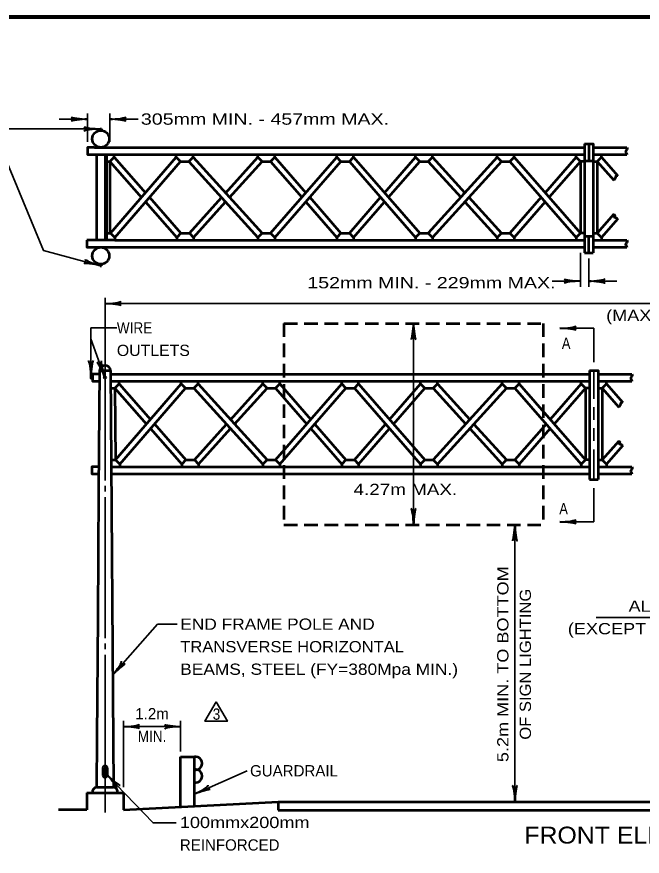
# Model space of a CAD drawing. Extents: x -35 to 821, y -13 to 531.
# Drawn here: x 165.2 to 298.4, y 346.2 to 525.1 of the extents above; entities that cross this region are included whole.
import ezdxf
from ezdxf.enums import TextEntityAlignment as Align

# ---------------------------------------------------------------- set-up
doc = ezdxf.new("R2010")
doc.units = 0
doc.header["$LTSCALE"] = 0.96
doc.linetypes.add('MEDIUM_DASHED', pattern=[4.5, 3, -1.5])
doc.layers.add('1', color=7, linetype='Continuous', lineweight=53)

msp = doc.modelspace()

# ---------------------------------------------------------------- linework, layer by layer
at = {"layer": '1', "lineweight": 35}
for p, q in [((180.2699, 498.4681), (180.2699, 504.4681)), ((185.0851, 498.4681), (185.0851, 504.4681)), ((174.2699, 503.2681), (180.2699, 503.2681)), ((185.0851, 503.2681), (191.0851, 503.2681)), ((285.2699, 474.7681), (285.2699, 467.5681)), ((287.0699, 473.5681), (287.0699, 467.5681)), ((285.2699, 468.7681), (279.2699, 468.7681)), ((287.0699, 468.7681), (293.0699, 468.7681)), ((184.0361, 426.3181), (184.0361, 465.1682)), ((184.0361, 463.9682), (413.7457, 463.9682)), ((249.7361, 459.7681), (249.7361, 416.8681)), ((181.0361, 448.3681), (181.0384, 458.8371)), ((181.0384, 458.8371), (186.5374, 458.8309)), ((288.1361, 458.7181), (280.9361, 458.7181)), ((288.1361, 451.5181), (288.1361, 458.7181)), ((181.0379, 456.4728), (183.9531, 448.343)), ((288.1361, 449.7181), (288.1361, 443.7181)), ((288.1361, 441.9181), (288.1361, 439.2181)), ((288.1361, 437.4181), (288.1361, 434.7181)), ((288.1361, 432.9181), (288.1361, 426.4681)), ((184.0361, 423.9181), (184.0361, 425.1181)), ((288.1361, 424.6681), (288.1361, 417.4681)), ((184.0361, 392.7181), (184.0361, 422.7181)), ((271.3361, 416.8681), (271.3361, 357.8452)), ((288.1361, 417.4681), (280.9361, 417.4681)), ((288.6341, 397.0681), (396.0341, 397.0681)), ((184.0361, 390.3181), (184.0361, 391.5181)), ((184.0361, 355.5181), (184.0361, 389.1181)), ((187.9361, 360.9181), (187.9361, 375.0433)), ((187.9361, 373.8433), (200.1229, 373.8433)), ((200.1229, 368.5706), (200.1229, 375.0433)), ((203.0564, 359.4792), (214.3126, 364.3926))]:
    msp.add_line(p, q, dxfattribs=at)
at = {"layer": '1'}
for p, q in [((182.9861, 501.1801), (183.2861, 501.1801)), ((182.9861, 500.8739), (182.9861, 501.1801)), ((183.2861, 501.1801), (183.2861, 500.8739)), ((181.7648, 497.2681), (286.1699, 497.2681)), ((286.1699, 498.0181), (286.1699, 474.7681)), ((287.0699, 498.0181), (287.0699, 494.4181)), ((287.9699, 497.2681), (295.1699, 497.2681)), ((182.2361, 495.7681), (182.2361, 477.4681)), ((184.0361, 495.7681), (184.0361, 477.4681)), ((184.3361, 495.7681), (184.3361, 477.4681)), ((185.9851, 495.1681), (185.9851, 495.7681)), ((185.9851, 495.7681), (233.3775, 495.7681)), ((199.1851, 495.1681), (199.1851, 495.7681)), ((202.7851, 495.1681), (202.7851, 495.7681)), ((216.5775, 495.1681), (216.5775, 495.7681)), ((220.1775, 495.1681), (220.1775, 495.7681)), ((233.3775, 495.1681), (233.3775, 495.7681)), ((236.9775, 495.1681), (236.9775, 495.7681)), ((250.1775, 495.1681), (250.1775, 495.7681)), ((253.7775, 495.1681), (253.7775, 495.7681)), ((267.5699, 495.1681), (267.5699, 495.7681)), ((271.1699, 495.1681), (271.1699, 495.7681)), ((284.3699, 495.1681), (284.3699, 495.7681)), ((287.9699, 495.7681), (295.1699, 495.7681)), ((289.7699, 495.1681), (289.7699, 495.7681)), ((184.3361, 494.2681), (185.0851, 494.2681)), ((185.0851, 494.2681), (185.9851, 495.1681)), ((185.0851, 494.2681), (191.8053, 486.6142)), ((185.0851, 494.2681), (185.0851, 478.9681)), ((185.2088, 478.9681), (199.1851, 495.1681)), ((185.9851, 495.1681), (192.643, 487.5851)), ((186.1088, 478.0681), (200.0851, 494.2681)), ((200.0851, 494.2681), (199.1851, 495.1681)), ((201.8851, 494.2681), (202.7851, 495.1681)), ((201.8851, 494.2681), (216.5775, 478.0681)), ((202.7851, 495.1681), (217.4775, 478.9681)), ((209.7105, 487.5321), (216.5775, 495.1681)), ((210.5687, 486.5858), (217.4775, 494.2681)), ((217.4775, 494.2681), (216.5775, 495.1681)), ((219.2775, 478.9681), (233.3775, 495.1681)), ((219.2775, 494.2681), (220.1775, 495.1681)), ((219.2775, 494.2681), (225.9358, 486.6181)), ((220.1775, 495.1681), (226.7775, 487.5851)), ((220.1775, 478.0681), (234.2775, 494.2681)), ((234.2775, 494.2681), (233.3775, 495.1681)), ((236.0775, 494.2681), (236.9775, 495.1681)), ((236.0775, 494.2681), (250.1775, 478.0681)), ((236.9775, 495.1681), (251.0775, 478.9681)), ((243.5775, 487.5851), (250.1775, 495.1681)), ((244.4192, 486.6181), (251.0775, 494.2681)), ((251.0775, 494.2681), (250.1775, 495.1681)), ((252.8775, 494.2681), (253.7775, 495.1681)), ((267.5699, 495.1681), (252.8775, 478.9681)), ((252.8775, 494.2681), (259.8156, 486.6181)), ((253.7775, 495.1681), (260.6737, 487.5643)), ((268.4699, 494.2681), (253.7775, 478.0681)), ((268.4699, 494.2681), (267.5699, 495.1681)), ((270.2699, 494.2681), (271.1699, 495.1681)), ((270.2699, 494.2681), (284.3699, 478.0681)), ((271.1699, 495.1681), (285.2699, 478.9681)), ((284.3699, 495.1681), (277.7699, 487.5851)), ((285.2699, 494.2681), (278.6115, 486.6181)), ((285.2699, 494.2681), (284.3699, 495.1681)), ((286.1699, 494.2681), (285.2699, 494.2681)), ((285.2699, 494.2681), (285.2699, 478.9681)), ((286.1699, 494.4181), (287.9699, 494.4181)), ((287.9699, 494.2681), (288.8699, 494.2681)), ((288.8699, 494.2681), (289.7699, 495.1681)), ((288.8699, 494.2681), (288.8699, 478.9681)), ((288.8699, 494.2681), (292.3771, 490.2387)), ((289.7699, 495.1681), (293.2187, 491.2057)), ((193.4886, 486.622), (200.2088, 478.9681)), ((202.0088, 478.9681), (208.856, 486.5819)), ((227.6192, 486.6181), (234.2775, 478.9681)), ((236.0775, 478.9681), (242.7359, 486.6181)), ((261.5318, 486.6181), (268.4699, 478.9681)), ((276.9283, 486.6181), (270.2699, 478.9681)), ((192.6509, 485.6511), (199.3088, 478.0681)), ((202.9088, 478.0681), (209.7143, 485.6356)), ((226.7775, 485.6511), (233.3775, 478.0681)), ((236.9775, 478.0681), (243.5775, 485.6511)), ((260.6737, 485.6719), (267.5699, 478.0681)), ((277.7699, 485.6511), (271.1699, 478.0681)), ((292.3769, 482.9973), (288.8699, 478.9681)), ((293.2185, 482.0303), (289.7699, 478.0681)), ((184.3361, 478.9681), (185.2088, 478.9681)), ((185.2088, 478.9681), (186.1088, 478.0681)), ((186.1088, 478.0681), (186.1088, 477.4681)), ((200.2088, 478.9681), (199.3088, 478.0681)), ((199.3088, 478.0681), (199.3088, 477.4681)), ((200.2088, 478.9681), (202.0088, 478.9681)), ((202.0088, 478.9681), (202.9088, 478.0681)), ((202.9088, 478.0681), (202.9088, 477.4681)), ((217.4775, 478.9681), (216.5775, 478.0681)), ((216.5775, 478.0681), (216.5775, 477.4681)), ((217.4775, 478.9681), (219.2775, 478.9681)), ((219.2775, 478.9681), (220.1775, 478.0681)), ((220.1775, 478.0681), (220.1775, 477.4681)), ((234.2775, 478.9681), (233.3775, 478.0681)), ((233.3775, 478.0681), (233.3775, 477.4681)), ((234.2775, 478.9681), (236.0775, 478.9681)), ((236.0775, 478.9681), (236.9775, 478.0681)), ((236.9775, 478.0681), (236.9775, 477.4681)), ((251.0775, 478.9681), (250.1775, 478.0681)), ((250.1775, 478.0681), (250.1775, 477.4681)), ((251.0775, 478.9681), (252.8775, 478.9681)), ((252.8775, 478.9681), (253.7775, 478.0681)), ((253.7775, 478.0681), (253.7775, 477.4681)), ((268.4699, 478.9681), (267.5699, 478.0681)), ((267.5699, 478.0681), (267.5699, 477.4681)), ((268.4699, 478.9681), (270.2699, 478.9681)), ((270.2699, 478.9681), (271.1699, 478.0681)), ((271.1699, 478.0681), (271.1699, 477.4681)), ((285.2699, 478.9681), (284.3699, 478.0681)), ((284.3699, 478.0681), (284.3699, 477.4681)), ((286.1699, 478.9681), (285.2699, 478.9681)), ((286.1699, 478.3681), (287.9699, 478.3681)), ((287.0699, 474.7681), (287.0699, 478.3681)), ((287.9699, 478.9681), (288.8699, 478.9681)), ((288.8699, 478.9681), (289.7699, 478.0681)), ((289.7699, 478.0681), (289.7699, 477.4681)), ((182.2361, 477.4681), (180.1361, 477.4681)), ((181.6209, 475.9681), (286.1699, 475.9681)), ((186.1088, 477.4681), (233.3775, 477.4681)), ((287.9699, 477.4681), (295.1699, 477.4681)), ((287.9699, 475.9681), (295.1699, 475.9681)), ((286.1699, 474.7681), (287.9699, 474.7681)), ((182.9861, 472.3561), (182.9861, 472.0561)), ((183.2861, 472.0561), (183.2861, 472.3561)), ((182.9861, 472.0561), (183.2861, 472.0561)), ((182.8361, 449.7181), (185.2361, 449.7181)), ((185.2361, 449.7181), (185.8361, 360.9181)), ((185.2361, 448.9681), (287.2361, 448.9681)), ((287.2361, 449.7181), (287.2361, 426.4681)), ((289.0361, 448.9681), (296.2361, 448.9681)), ((187.0513, 446.8681), (187.0513, 447.4681)), ((200.2513, 446.8681), (200.2513, 447.4681)), ((203.8513, 446.8681), (203.8513, 447.4681)), ((217.6437, 446.8681), (217.6437, 447.4681)), ((221.2437, 446.8681), (221.2437, 447.4681)), ((234.4437, 446.8681), (234.4437, 447.4681)), ((238.0437, 446.8681), (238.0437, 447.4681)), ((251.2437, 446.8681), (251.2437, 447.4681)), ((254.8437, 446.8681), (254.8437, 447.4681)), ((268.6361, 446.8681), (268.6361, 447.4681)), ((272.2361, 446.8681), (272.2361, 447.4681)), ((285.4361, 446.8681), (285.4361, 447.4681)), ((289.0361, 447.4681), (296.2361, 447.4681)), ((290.8361, 446.8681), (290.8361, 447.4681)), ((185.2513, 445.9681), (186.1513, 445.9681)), ((186.1513, 445.9681), (187.0513, 446.8681)), ((186.1513, 445.9681), (186.275, 430.6681)), ((186.1513, 445.9681), (192.8715, 438.3142)), ((186.275, 430.6681), (200.2513, 446.8681)), ((187.0513, 446.8681), (193.7092, 439.2851)), ((187.175, 429.7681), (201.1513, 445.9681)), ((201.1513, 445.9681), (200.2513, 446.8681)), ((202.9513, 445.9681), (203.8513, 446.8681)), ((202.9513, 445.9681), (217.6437, 429.7681)), ((203.8513, 446.8681), (218.5437, 430.6681)), ((210.7767, 439.2321), (217.6437, 446.8681)), ((211.6349, 438.2858), (218.5437, 445.9681)), ((218.5437, 445.9681), (217.6437, 446.8681)), ((220.3437, 445.9681), (221.2437, 446.8681)), ((220.3437, 430.6681), (234.4437, 446.8681)), ((220.3437, 445.9681), (227.002, 438.3181)), ((221.2437, 446.8681), (227.8437, 439.2851)), ((221.2437, 429.7681), (235.3437, 445.9681)), ((235.3437, 445.9681), (234.4437, 446.8681)), ((237.1437, 445.9681), (238.0437, 446.8681)), ((237.1437, 445.9681), (251.2437, 429.7681)), ((238.0437, 446.8681), (252.1437, 430.6681)), ((244.6437, 439.2851), (251.2437, 446.8681)), ((245.4854, 438.3181), (252.1437, 445.9681)), ((252.1437, 445.9681), (251.2437, 446.8681)), ((253.9437, 445.9681), (254.8437, 446.8681)), ((268.6361, 446.8681), (253.9437, 430.6681)), ((253.9437, 445.9681), (260.8818, 438.3181)), ((254.8437, 446.8681), (261.7399, 439.2643)), ((269.5361, 445.9681), (254.8437, 429.7681)), ((269.5361, 445.9681), (268.6361, 446.8681)), ((271.3361, 445.9681), (272.2361, 446.8681)), ((271.3361, 445.9681), (285.4361, 429.7681)), ((272.2361, 446.8681), (286.3361, 430.6681)), ((285.4361, 446.8681), (278.8361, 439.2851)), ((286.3361, 445.9681), (279.6777, 438.3181)), ((286.3361, 445.9681), (285.4361, 446.8681)), ((287.2361, 445.9681), (286.3361, 445.9681)), ((286.3361, 445.9681), (286.3361, 430.6681)), ((289.0361, 445.9681), (289.9361, 445.9681)), ((289.9361, 445.9681), (290.8361, 446.8681)), ((289.9361, 445.9681), (289.9361, 430.6681)), ((289.9361, 445.9681), (293.4433, 441.9387)), ((290.8361, 446.8681), (294.2849, 442.9057)), ((194.5548, 438.322), (201.275, 430.6681)), ((203.075, 430.6681), (209.9222, 438.2819)), ((228.6854, 438.3181), (235.3437, 430.6681)), ((237.1437, 430.6681), (243.8021, 438.3181)), ((262.598, 438.3181), (269.5361, 430.6681)), ((277.9945, 438.3181), (271.3361, 430.6681)), ((193.7171, 437.3511), (200.375, 429.7681)), ((203.975, 429.7681), (210.7805, 437.3356)), ((227.8437, 437.3511), (234.4437, 429.7681)), ((238.0437, 429.7681), (244.6437, 437.3511)), ((261.7399, 437.3719), (268.6361, 429.7681)), ((278.8361, 437.3511), (272.2361, 429.7681)), ((293.4431, 434.6973), (289.9361, 430.6681)), ((294.2847, 433.7303), (290.8361, 429.7681)), ((185.375, 430.6681), (186.275, 430.6681)), ((186.275, 430.6681), (187.175, 429.7681)), ((187.175, 429.7681), (187.175, 429.1681)), ((201.275, 430.6681), (200.375, 429.7681)), ((200.375, 429.7681), (200.375, 429.1681)), ((201.275, 430.6681), (203.075, 430.6681)), ((203.075, 430.6681), (203.975, 429.7681)), ((203.975, 429.7681), (203.975, 429.1681)), ((218.5437, 430.6681), (217.6437, 429.7681)), ((217.6437, 429.7681), (217.6437, 429.1681)), ((218.5437, 430.6681), (220.3437, 430.6681)), ((220.3437, 430.6681), (221.2437, 429.7681)), ((221.2437, 429.7681), (221.2437, 429.1681)), ((235.3437, 430.6681), (234.4437, 429.7681)), ((234.4437, 429.7681), (234.4437, 429.1681)), ((235.3437, 430.6681), (237.1437, 430.6681)), ((237.1437, 430.6681), (238.0437, 429.7681)), ((238.0437, 429.7681), (238.0437, 429.1681)), ((252.1437, 430.6681), (251.2437, 429.7681)), ((251.2437, 429.7681), (251.2437, 429.1681)), ((252.1437, 430.6681), (253.9437, 430.6681)), ((253.9437, 430.6681), (254.8437, 429.7681)), ((254.8437, 429.7681), (254.8437, 429.1681)), ((269.5361, 430.6681), (268.6361, 429.7681)), ((268.6361, 429.7681), (268.6361, 429.1681)), ((269.5361, 430.6681), (271.3361, 430.6681)), ((271.3361, 430.6681), (272.2361, 429.7681)), ((272.2361, 429.7681), (272.2361, 429.1681)), ((286.3361, 430.6681), (285.4361, 429.7681)), ((285.4361, 429.7681), (285.4361, 429.1681)), ((287.2361, 430.6681), (286.3361, 430.6681)), ((289.0361, 430.6681), (289.9361, 430.6681)), ((289.9361, 430.6681), (290.8361, 429.7681)), ((290.8361, 429.7681), (290.8361, 429.1681)), ((185.3851, 427.6681), (287.2361, 427.6681)), ((289.0361, 429.1681), (296.2361, 429.1681)), ((289.0361, 427.6681), (296.2361, 427.6681)), ((287.2361, 426.4681), (289.0361, 426.4681)), ((182.4813, 397.2187), (182.3069, 371.4192)), ((200.1229, 356.886), (200.1229, 367.3706)), ((200.1229, 367.3706), (203.0564, 367.3706)), ((203.0564, 356.886), (203.0564, 367.3706)), ((183.5986, 365.0147), (183.5986, 363.5147)), ((184.4986, 365.0147), (184.4986, 363.5147)), ((180.1361, 359.7181), (187.9361, 359.7181)), ((180.1361, 359.7181), (180.1361, 356.1181)), ((187.9361, 359.7181), (187.9361, 356.1181)), ((220.8909, 357.8452), (220.8909, 356.0452)), ((180.1361, 356.1181), (174.1361, 356.1181)), ((220.8909, 356.0452), (376.8909, 356.0452))]:
    msp.add_line(p, q, dxfattribs=at)
at = {"layer": '1', "linetype": 'MEDIUM_DASHED'}
for p, q in [((222.1361, 459.7681), (222.1361, 416.8681)), ((222.1361, 459.7681), (277.3361, 459.7681)), ((277.3361, 459.7681), (277.3361, 416.8681)), ((222.1361, 416.8681), (277.3361, 416.8681))]:
    msp.add_line(p, q, dxfattribs=at)
at = {"layer": '1', "lineweight": 158}
msp.add_lwpolyline([(814.3112, 525.0846), (22.6112, 524.9846), (22.7112, -1.0154)], dxfattribs=at)
at = {"layer": '1', "lineweight": 35}
for points in [[(182.9861, 501.1801), (160.1576, 501.1801), (170.9204, 475.2825), (182.9861, 472.0561)], [(185.6743, 384.8715), (195.2289, 395.6992), (199.4262, 395.6992)], [(184.4986, 363.5147), (194.2812, 353.3212), (199.1554, 353.3212)]]:
    msp.add_lwpolyline(points, dxfattribs=at)
at = {"layer": '1'}
for points in [[(181.7648, 497.2681), (180.2699, 497.2681), (180.2699, 495.7681), (185.9851, 495.7681)], [(286.1699, 498.0181), (287.9699, 498.0181), (287.9699, 474.7681)], [(233.3775, 495.7681), (236.9775, 495.7681), (284.3699, 495.7681), (286.1699, 495.7681)], [(200.0851, 494.2681), (200.9851, 494.2681), (201.8851, 494.2681)], [(217.4775, 494.2681), (218.3775, 494.2681), (219.2775, 494.2681)], [(234.2775, 494.2681), (235.1775, 494.2681), (236.0775, 494.2681)], [(251.0775, 494.2681), (251.9775, 494.2681), (252.8775, 494.2681)], [(268.4699, 494.2681), (269.3699, 494.2681), (270.2699, 494.2681)], [(180.1361, 477.4681), (180.1361, 475.9681), (181.6209, 475.9681)], [(186.1088, 477.4681), (184.0361, 477.4681), (182.2361, 477.4681)], [(233.3775, 477.4681), (236.9775, 477.4681), (284.3699, 477.4681), (286.1699, 477.4681)], [(182.831, 448.9681), (181.3361, 448.9681), (181.3361, 447.4681), (182.8209, 447.4681)], [(182.8361, 449.7181), (182.6638, 424.2181), (182.4812, 397.2187)], [(287.2361, 449.7181), (289.0361, 449.7181), (289.0361, 426.4681)], [(181.3361, 448.3681), (181.0361, 448.3681), (181.0361, 448.0681), (181.3361, 448.0681)], [(185.2513, 447.4681), (187.0513, 447.4681), (234.4437, 447.4681)], [(234.4437, 447.4681), (238.0437, 447.4681), (285.4361, 447.4681), (287.2361, 447.4681)], [(201.1513, 445.9681), (202.0513, 445.9681), (202.9513, 445.9681)], [(218.5437, 445.9681), (219.4437, 445.9681), (220.3437, 445.9681)], [(235.3437, 445.9681), (236.2437, 445.9681), (237.1437, 445.9681)], [(252.1437, 445.9681), (253.0437, 445.9681), (253.9437, 445.9681)], [(269.5361, 445.9681), (270.4361, 445.9681), (271.3361, 445.9681)], [(182.6972, 429.1681), (181.2023, 429.1681), (181.2023, 427.6681), (182.6871, 427.6681)], [(185.375, 429.1681), (187.175, 429.1681), (234.4437, 429.1681)], [(234.4437, 429.1681), (238.0437, 429.1681), (285.4361, 429.1681), (287.2361, 429.1681)], [(182.307, 371.4192), (182.2361, 360.9181), (185.8361, 360.9181)], [(187.9361, 356.1181), (220.8909, 357.8452), (376.8909, 357.8452)]]:
    msp.add_lwpolyline(points, dxfattribs=at)
at = {"layer": '1', "lineweight": 35}
msp.add_lwpolyline([(207.7133, 379.1278), (205.3133, 374.9709), (210.1133, 374.9709)], close=True, dxfattribs=at)
at = {"layer": '1'}
for centre, radius in [((183.1361, 499.0681), 1.812), ((183.1361, 474.1681), 1.812), ((184.0361, 448.2181), 0.15)]:
    msp.add_circle(centre, radius, dxfattribs=at)
for centre, radius, start, end in [((184.0361, 449.5575), 1.2107, 7.62224, 172.37776), ((203.3412, 366.0181), 1.3822, 258.1086, 101.8914), ((184.0486, 365.0147), 0.45, 0, 180), ((184.0486, 363.5147), 0.45, 180, 0), ((203.3412, 363.3131), 1.3822, 258.1086, 101.8914), ((182.4154, 359.8461), 1.0869, 99.49518, 186.76502), ((185.6568, 359.8461), 1.0869, 353.23498, 80.50482)]:
    msp.add_arc(centre, radius, start, end, dxfattribs=at)
at = {"layer": '1', "lineweight": 40}
for centre, major_axis, ratio, start_param, end_param in [((178.9605, 502.9365), (2.1428, 0.1874), 0.122415, 0.89635335, 3.14159265), ((178.9605, 502.9365), (2.1428, 0.1874), 0.122415, 0.89635335, 3.14159265), ((178.9253, 503.522), (2.1077, -0.2108), 0.07063, 3.14071475, 5.41810995), ((178.9253, 503.522), (2.1077, -0.2108), 0.07063, 3.14071475, 5.41810995), ((186.4297, 503.0142), (-2.1077, 0.2108), 0.07063, 3.14071475, 5.41810995), ((186.3945, 503.5997), (-2.1428, -0.1874), 0.122415, 0.89635335, 3.14159265), ((181.6767, 500.8485), (2.1428, 0.1874), 0.122415, 0.89635335, 3.14159265), ((181.6415, 501.434), (2.1077, -0.2108), 0.07063, 3.14071475, 5.41810995), ((181.6355, 472.0741), (2.1185, -0.3725), 0.122415, 0.89635335, 3.14159265), ((181.7527, 472.6487), (-1.9817, 0.7481), 0.07063, 6.28230741, 8.55970261), ((283.9605, 468.4365), (2.1428, 0.1874), 0.122415, 0.89635335, 3.14159265), ((283.9253, 469.022), (2.1077, -0.2108), 0.07063, 3.14071475, 5.41810995), ((288.4145, 468.5142), (-2.1077, 0.2108), 0.07063, 3.14071475, 5.41810995), ((288.4145, 468.5142), (-2.1077, 0.2108), 0.07063, 3.14071475, 5.41810995), ((288.3793, 469.0997), (-2.1428, -0.1874), 0.122415, 0.89635335, 3.14159265), ((288.3793, 469.0997), (-2.1428, -0.1874), 0.122415, 0.89635335, 3.14159265), ((185.3807, 463.7143), (-2.1077, 0.2108), 0.07063, 3.14071475, 5.41810995), ((185.3455, 464.2998), (-2.1428, -0.1874), 0.122415, 0.89635335, 3.14159265), ((249.4822, 458.4235), (0.2108, 2.1077), 0.07063, 3.14071475, 5.41810995), ((250.0677, 458.4587), (-0.1874, 2.1428), 0.122415, 0.89635335, 3.14159265), ((282.2807, 458.4642), (-2.1077, 0.2108), 0.07063, 3.14071475, 5.41810995), ((282.2455, 459.0497), (-2.1428, -0.1874), 0.122415, 0.89635335, 3.14159265), ((180.7048, 449.6776), (0.1869, -2.1429), 0.122415, 0.89635335, 3.14159265), ((180.7048, 449.6776), (0.1869, -2.1429), 0.122415, 0.89635335, 3.14159265), ((181.2903, 449.7126), (0.2112, 2.1077), 0.07063, 6.28230741, 8.55970261), ((181.2903, 449.7126), (0.2112, 2.1077), 0.07063, 6.28230741, 8.55970261), ((183.199, 449.4637), (0.8997, -1.9538), 0.122415, 0.89635335, 3.14159265), ((183.7383, 449.6944), (-0.513, 2.0552), 0.07063, 6.28230741, 8.55970261), ((249.4045, 418.1775), (0.1874, -2.1428), 0.122415, 0.89635335, 3.14159265), ((249.99, 418.2127), (-0.2108, -2.1077), 0.07063, 3.14071475, 5.41810995), ((271.0822, 415.5235), (0.2108, 2.1077), 0.07063, 3.14071475, 5.41810995), ((271.6677, 415.5587), (-0.1874, 2.1428), 0.122415, 0.89635335, 3.14159265), ((282.2807, 417.2142), (-2.1077, 0.2108), 0.07063, 3.14071475, 5.41810995), ((282.2455, 417.7997), (-2.1428, -0.1874), 0.122415, 0.89635335, 3.14159265), ((186.2921, 386.0727), (-1.2773, -1.7307), 0.122415, 0.89635335, 3.14159265), ((186.7543, 385.7117), (-1.5526, -1.4409), 0.07063, 3.14071475, 5.41810995), ((189.2807, 373.5894), (-2.1077, 0.2108), 0.07063, 3.14071475, 5.41810995), ((189.2807, 373.5894), (-2.1077, 0.2108), 0.07063, 3.14071475, 5.41810995), ((189.2455, 374.1749), (-2.1428, -0.1874), 0.122415, 0.89635335, 3.14159265), ((189.2455, 374.1749), (-2.1428, -0.1874), 0.122415, 0.89635335, 3.14159265), ((198.8135, 373.5117), (2.1428, 0.1874), 0.122415, 0.89635335, 3.14159265), ((198.7783, 374.0972), (2.1077, -0.2108), 0.07063, 3.14071475, 5.41810995), ((185.1661, 362.3404), (-1.3485, 1.6758), 0.122415, 3.14159265, 5.38683196), ((185.6128, 362.7204), (-1.6115, 1.3748), 0.07063, 0.86507535, 3.14247055), ((204.1238, 360.3069), (-1.8889, -1.029), 0.122415, 0.89635335, 3.14159265), ((271.0045, 359.1546), (0.1874, -2.1428), 0.122415, 0.89635335, 3.14159265), ((271.59, 359.1898), (-0.2108, -2.1077), 0.07063, 3.14071475, 5.41810995), ((204.3903, 359.7844), (-2.016, -0.65), 0.07063, 3.14071475, 5.41810995)]:
    msp.add_ellipse(centre, major_axis=major_axis, ratio=ratio, start_param=start_param, end_param=end_param, dxfattribs=at)
at = {"layer": '1'}
for points in [[(295.1699, 497.2681), (295.2383, 496.9779), (295.0194, 496.6494), (294.9168, 496.2799), (295.1015, 495.9583), (295.1699, 495.7681)], [(293.2187, 491.2057), (292.8269, 491.1638), (292.6772, 490.6649), (292.3771, 490.2387)], [(292.3769, 482.9973), (292.6273, 482.7317), (292.4278, 482.4823), (292.777, 482.3326), (293.2185, 482.0303)], [(295.1672, 477.4796), (295.2356, 477.1894), (295.0167, 476.8609), (294.9141, 476.4914), (295.0988, 476.1698), (295.1672, 475.9796)], [(296.2361, 448.9681), (296.3045, 448.6779), (296.0856, 448.3494), (295.983, 447.9799), (296.1677, 447.6583), (296.2361, 447.4681)], [(294.2849, 442.9057), (293.8931, 442.8638), (293.7434, 442.3649), (293.4433, 441.9387)], [(293.4431, 434.6973), (293.6935, 434.4317), (293.494, 434.1823), (293.8432, 434.0326), (294.2847, 433.7303)], [(296.2334, 429.1796), (296.3018, 428.8894), (296.0829, 428.5609), (295.9803, 428.1914), (296.165, 427.8698), (296.2334, 427.6796)]]:
    msp.add_spline(points, degree=3, dxfattribs=at)

# ---------------------------------------------------------------- texts
for s, height, width, p in [('305mm MIN. - 457mm MAX.', 2.4, 1.3, (191.6748, 502.091)), ('152mm MIN. - 229mm MAX.', 2.4, 1.3, (227.1156, 467.2292)), ('WIRE', 2.4, 0.9, (186.5573, 457.6096)), ('A', 2.4, 0.85, (281.3384, 454.3262)), ('OUTLETS', 2.4, 1.05, (186.5573, 452.8096)), ('4.27m MAX.', 2.4, 1.25, (236.9678, 423.182)), ('A', 2.4, 0.85, (280.788, 419.0882)), ('END FRAME POLE AND', 2.4, 1.15, (200.0478, 394.4749)), ('TRANSVERSE HORIZONTAL', 2.4, 1.1, (200.0478, 389.6749)), ('BEAMS, STEEL (FY=380Mpa MIN.)', 2.4, 1.15, (200.0478, 384.8749)), ('3', 2.4, 0.9, (206.9727, 375.3045)), ('100mmx200mm', 2.4, 1.2, (199.9743, 352.23)), ('FRONT ELEVATION', 3.6, 1.1, (273.3279, 348.9287))]:
    msp.add_text(s, height=height, dxfattribs=dict(at, width=width)).set_placement(p)
for s, width, p in [('(MAX. 45.720m)', 1.2, (304.7845, 460.2527)), ('ALL DIAGONALS & BRACES TO BE AT NOMINAL 45', 1.2, (342.3034, 398.3135)), ('(EXCEPT VERTICAL & HORIZONTAL BRACING AT OUTER TRUSS', 1.2, (342.3032, 393.5135)), ('MIN.', 0.9, (194.0499, 370.5865))]:
    msp.add_text(s, height=2.4, dxfattribs=dict(at, width=width)).set_placement(p, align=Align.CENTER)
for s, width, p in [('5.2m MIN. TO BOTTOM', 1.2, (269.9514, 387.1423)), ('OF SIGN LIGHTING', 1.1, (274.7514, 387.1422))]:
    msp.add_text(s, height=2.4, rotation=90, dxfattribs=dict(at, width=width)).set_placement(p, align=Align.CENTER)
msp.add_text('1.2m', height=2.4, dxfattribs=at).set_placement((194.05, 375.3865), align=Align.CENTER)
for s, p in [('GUARDRAIL', (214.9197, 363.2317)), ('REINFORCED', (199.9743, 347.43))]:
    msp.add_text(s, height=2.4, dxfattribs=at).set_placement(p)

doc.saveas('drawing.dxf')
